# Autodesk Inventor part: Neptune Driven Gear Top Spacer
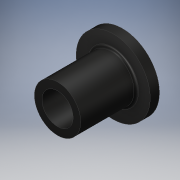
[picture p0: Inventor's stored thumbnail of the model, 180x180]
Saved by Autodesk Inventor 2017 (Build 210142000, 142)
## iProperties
Created: 2016-07
Part Number: Neptune Driven Gear Top Spacer
Material: Generic
Document SubType Name: Modeling
Designer: Stan
Density: 1 g/cm^3
Appearance: Glossy - Black
Author: Stan
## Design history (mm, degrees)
sketch "Sketch1"
  geometry: C1 r 12.7 at (0, 0); 1 further point
  constraints: 1 centre point, 1 coincident
  dimensions: "d0" = 25.4 diameter of C1
extrude "Extrusion1" new body sketch "Sketch1" distance "d1" = 3.175; taper "d2" = 0 deg
sketch "Sketch2"
  geometry: C1 r 7.938 at (0, 0); 1 further point
  constraints: 1 centre point, 1 coincident
  dimensions: "d3" = 15.875 diameter of C1
extrude "Extrusion2" join sketch "Sketch2" distance "d4" = 19.05; taper "d5" = 0 deg
sketch "Sketch3"
  geometry: C1 r 5.334 at (0, 0); 1 further point
  constraints: 1 centre point, 1 coincident
  dimensions: "d6" = 10.668 diameter of C1
extrude "Extrusion3" cut sketch "Sketch3" distance "d7" = 22.225; taper "d8" = 0 deg
fillet "Fillet1" dims "d9" = 0.79375
body "Solid1"
